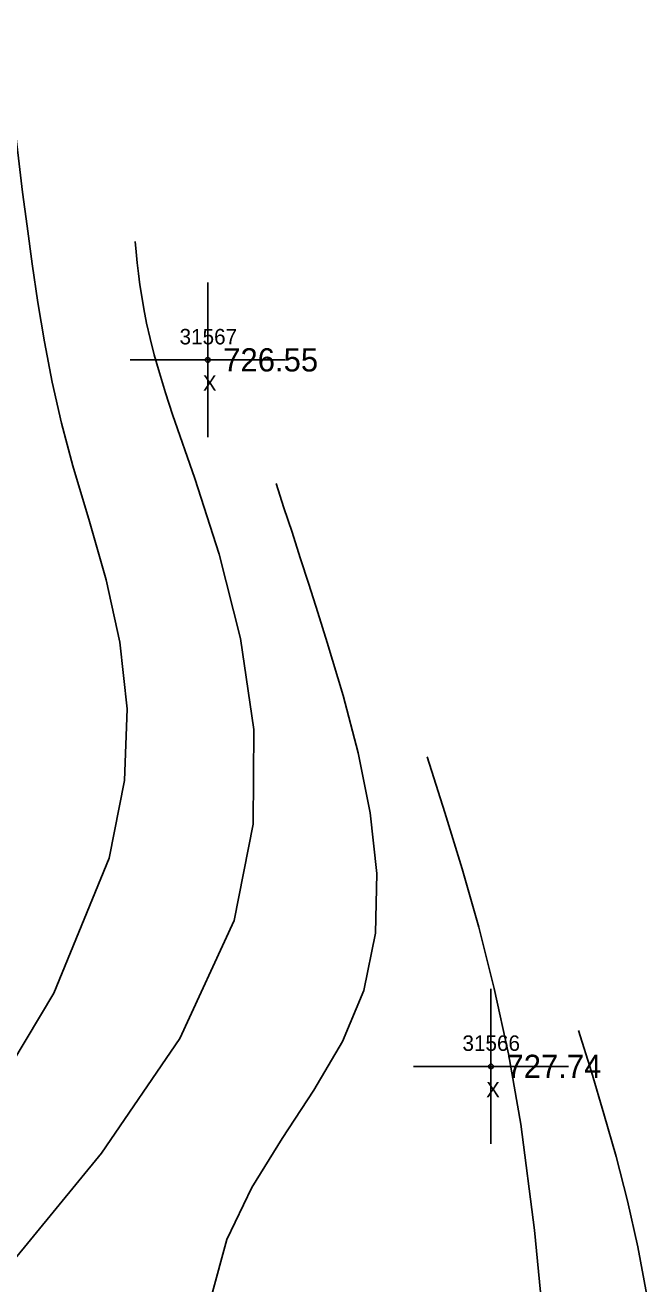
# Model space of a CAD drawing. Extents: x 1376587 to 1378239, y 1000335 to 1003031.
# Drawn here: x 1377746.5 to 1377786.7, y 1001151.5 to 1001232.8 of the extents above; entities that cross this region are included whole.
import ezdxf

# ---------------------------------------------------------------- set-up
doc = ezdxf.new("R2010")
doc.units = 0
for name, color, linetype in [('RD_DTM_Major1', 7, 'Continuous'), ('RD_DTM_Minor1', 7, 'Continuous'), ('RD_EX_Misc', 7, 'Continuous'), ('RD_EX_Misc_txCode', 7, 'Continuous'), ('RD_EX_TX_Misc_ELEV', 7, 'Continuous'), ('RD_SMD_Locator', 7, 'Continuous')]:
    doc.layers.add(name, color=color, linetype=linetype)

msp = doc.modelspace()

# ---------------------------------------------------------------- linework, layer by layer
at = {"layer": 'RD_DTM_Major1'}
msp.add_lwpolyline([(1377745.074, 1001232.841), (1377745.32, 1001230.704), (1377745.569, 1001228.562), (1377745.824, 1001226.411), (1377746.085, 1001224.245), (1377746.356, 1001222.062), (1377746.64, 1001219.855), (1377746.97, 1001217.411), (1377747.338, 1001214.924), (1377747.764, 1001212.385), (1377748.27, 1001209.786), (1377748.874, 1001207.117), (1377749.599, 1001204.368), (1377750.671, 1001200.776), (1377751.753, 1001196.995), (1377752.633, 1001192.978), (1377753.1, 1001188.677), (1377752.942, 1001184.044), (1377751.946, 1001179.03), (1377748.378, 1001170.297), (1377742.853, 1001161.11), (1377736.065, 1001152.095), (1377728.707, 1001143.88), (1377726.664, 1001141.962)], dxfattribs=at)
at = {"layer": 'RD_DTM_Minor1'}
for points in [[(1377753.626, 1001218.872), (1377753.692, 1001218.188), (1377753.762, 1001217.496), (1377753.842, 1001216.79), (1377753.936, 1001216.061), (1377754.049, 1001215.304), (1377754.185, 1001214.511), (1377754.367, 1001213.593), (1377754.589, 1001212.607), (1377754.86, 1001211.538), (1377755.187, 1001210.371), (1377755.577, 1001209.091), (1377756.037, 1001207.681), (1377757.47, 1001203.549), (1377759.049, 1001198.673), (1377760.434, 1001193.217), (1377761.283, 1001187.343), (1377761.257, 1001181.215), (1377760.013, 1001174.995), (1377756.522, 1001167.38), (1377751.445, 1001159.957), (1377745.581, 1001152.809)], [(1377762.73, 1001203.231), (1377763.242, 1001201.666), (1377763.761, 1001200.075), (1377764.292, 1001198.434), (1377764.843, 1001196.717), (1377765.419, 1001194.898), (1377766.027, 1001192.952), (1377767.058, 1001189.531), (1377768.036, 1001185.83), (1377768.811, 1001181.961), (1377769.232, 1001178.036), (1377769.147, 1001174.168), (1377768.406, 1001170.469), (1377767.019, 1001167.175), (1377765.17, 1001164.027), (1377763.129, 1001160.919), (1377761.167, 1001157.743), (1377759.552, 1001154.39), (1377758.556, 1001150.752)], [(1377772.503, 1001185.564), (1377773.64, 1001181.982), (1377774.754, 1001178.335), (1377775.823, 1001174.56), (1377776.825, 1001170.593), (1377777.738, 1001166.369), (1377778.539, 1001161.825), (1377779.436, 1001154.981), (1377780.135, 1001147.636)], [(1377782.275, 1001167.897), (1377783.104, 1001165.218), (1377783.917, 1001162.51), (1377784.698, 1001159.742), (1377785.43, 1001156.884), (1377786.098, 1001153.906), (1377786.686, 1001150.779)]]:
    msp.add_lwpolyline(points, dxfattribs=at)
at = {"layer": 'RD_EX_Misc'}
for p, q in [((1377758.313, 1001206.217), (1377758.313, 1001216.217)), ((1377753.313, 1001211.217), (1377763.313, 1001211.217)), ((1377776.616, 1001160.57), (1377776.616, 1001170.57)), ((1377771.616, 1001165.57), (1377781.616, 1001165.57))]:
    msp.add_line(p, q, dxfattribs=at)
at = {"layer": 'RD_SMD_Locator'}
for centre in [(1377758.313, 1001211.217), (1377776.616, 1001165.57)]:
    msp.add_circle(centre, 0.15, dxfattribs=at)

# ---------------------------------------------------------------- texts
at = {"layer": 'RD_EX_Misc_txCode'}
for s, p in [('31567', (1377756.494, 1001212.217)), ('X', (1377757.998, 1001209.217)), ('31566', (1377774.773, 1001166.57)), ('X', (1377776.301, 1001163.57))]:
    msp.add_text(s, height=1, dxfattribs=at).set_placement(p)
at = {"layer": 'RD_EX_TX_Misc_ELEV'}
for s, p in [('726.55', (1377759.313, 1001210.467)), ('727.74', (1377777.616, 1001164.82))]:
    msp.add_text(s, height=1.5, dxfattribs=at).set_placement(p)

doc.saveas('drawing.dxf')
